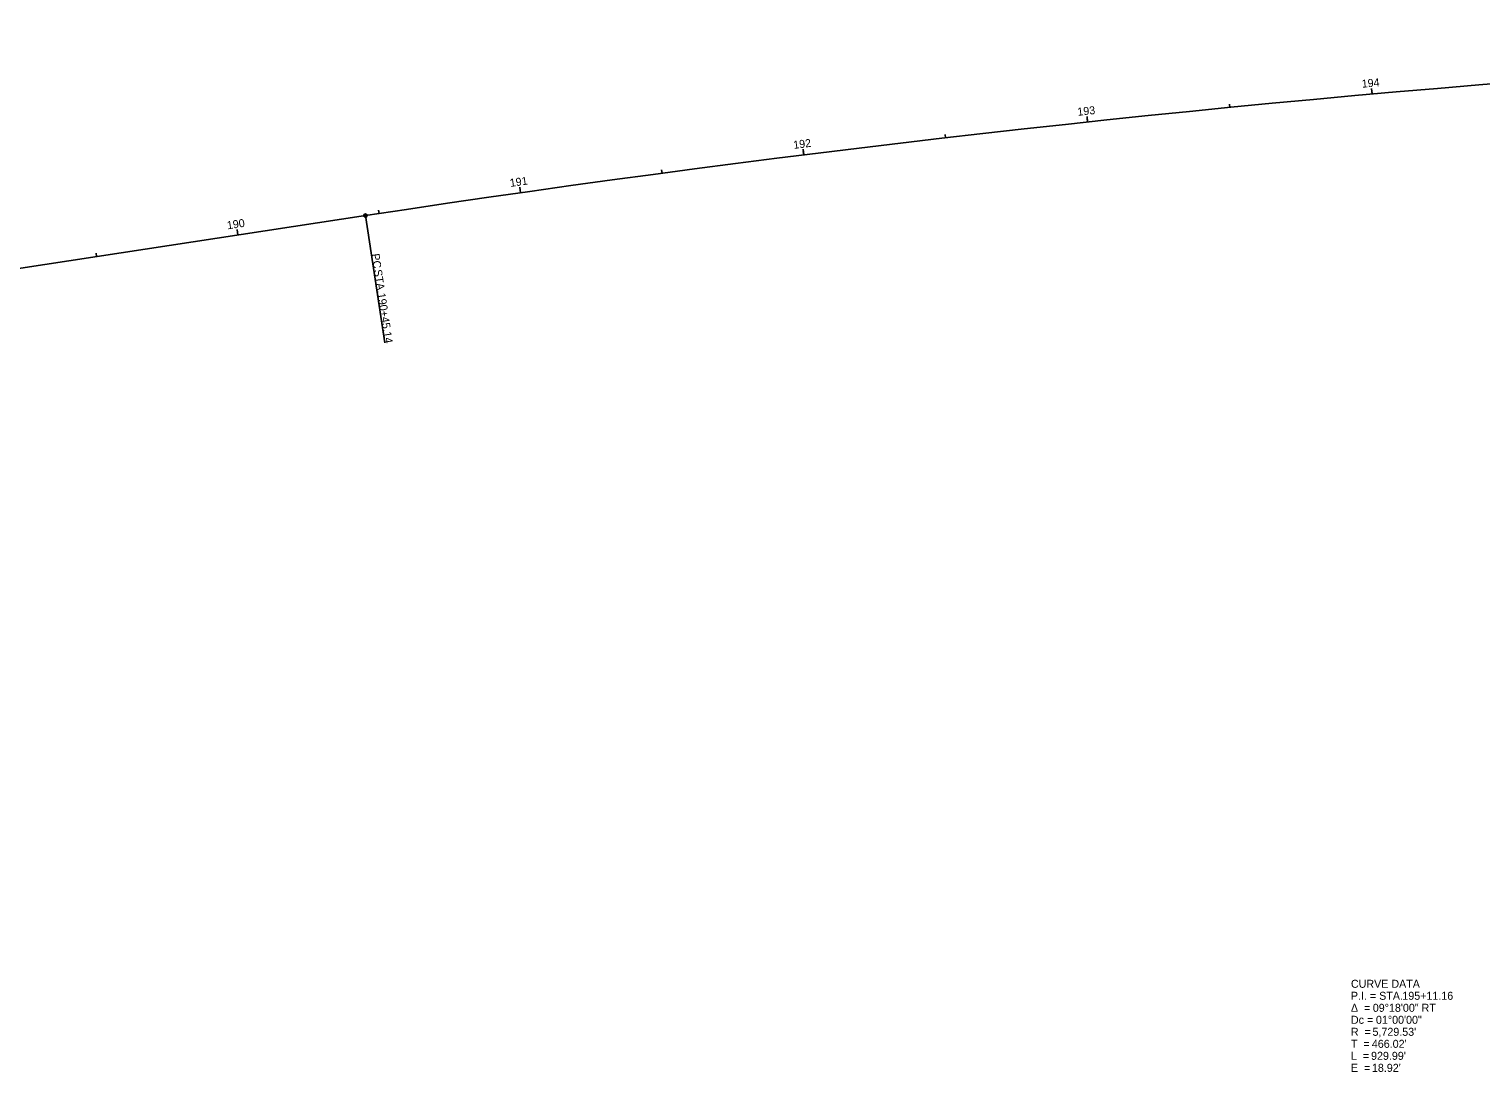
# Model space of a CAD drawing. Extents: x 1501024 to 1508874, y 327839 to 328839.
# Drawn here: x 1506902 to 1507410, y 327898 to 328263 of the extents above; entities that cross this region are included whole.
import ezdxf

# ---------------------------------------------------------------- set-up
doc = ezdxf.new("R2010")
doc.units = 0
for name, color, linetype in [('GE_X_Alignment', 7, 'Continuous'), ('GE_X_Alignment_100_Cardinal_Points', 7, 'Continuous'), ('GE_X_Alignment_100_Curve_Data', 7, 'Continuous'), ('GE_X_Alignment_100_Stations', 7, 'Continuous'), ('GE_X_Alignment_500_Cardinal_Points', 7, 'Continuous'), ('GE_X_Alignment_500_Curve_Data', 7, 'Continuous'), ('GE_X_Alignment_500_Stations', 7, 'Continuous')]:
    doc.layers.add(name, color=color, linetype=linetype)

msp = doc.modelspace()

# ---------------------------------------------------------------- linework, layer by layer
at = {"layer": 'GE_X_Alignment'}
msp.add_line((1506214.56, 328075.36), (1507019.33, 328197.87), dxfattribs=at)
msp.add_arc((1507881.6, 322533.59), 5729.53, 89.35563, 98.65563, dxfattribs=at)
at = {"layer": 'GE_X_Alignment_100_Cardinal_Points'}
msp.add_line((1507019.33, 328197.87), (1507026.1, 328153.38), dxfattribs=at)
msp.add_circle((1507019.33, 328197.87), 0.6, dxfattribs=at)
at = {"layer": 'GE_X_Alignment_100_Stations'}
for p, q in [((1507371.58, 328240.38), (1507371.4, 328242.37)), ((1507321.8, 328235.71), (1507321.68, 328236.9)), ((1507272.06, 328230.61), (1507271.84, 328232.59)), ((1507222.36, 328225.07), (1507222.23, 328226.26)), ((1507172.72, 328219.1), (1507172.47, 328221.08)), ((1507123.13, 328212.7), (1507122.97, 328213.89)), ((1507073.6, 328205.86), (1507073.32, 328207.84)), ((1507024.13, 328198.59), (1507023.95, 328199.78)), ((1506974.7, 328191.07), (1506974.4, 328193.05)), ((1506925.27, 328183.55), (1506925.09, 328184.73))]:
    msp.add_line(p, q, dxfattribs=at)
at = {"layer": 'GE_X_Alignment_500_Cardinal_Points'}
msp.add_line((1507019.33, 328197.87), (1507026.1, 328153.38), dxfattribs=at)
msp.add_circle((1507019.33, 328197.87), 0.6, dxfattribs=at)
at = {"layer": 'GE_X_Alignment_500_Stations'}
for p, q in [((1507371.58, 328240.38), (1507371.47, 328241.57)), ((1507272.06, 328230.61), (1507271.93, 328231.8)), ((1507172.72, 328219.1), (1507172.57, 328220.29)), ((1507073.6, 328205.86), (1507073.43, 328207.05)), ((1506974.7, 328191.07), (1506974.4, 328193.05))]:
    msp.add_line(p, q, dxfattribs=at)

# ---------------------------------------------------------------- texts
at = {"layer": 'GE_X_Alignment_100_Cardinal_Points'}
for s, p in [('PC', (1507021.42, 328184.38)), (' STA. ', (1507022.12, 328179.83)), ('190+45.14', (1507023.52, 328170.61))]:
    msp.add_text(s, height=2.8, rotation=278.6556, dxfattribs=at).set_placement(p)
at = {"layer": 'GE_X_Alignment_100_Curve_Data'}
for s, p in [('CURVE DATA', (1507364.19, 327927.77)), ('Δ  = ', (1507364.19, 327919.37)), ('P.I. = STA. ', (1507364.19, 327923.57)), ('09°18\'00" RT', (1507371.84, 327919.37)), ('195+11.16', (1507382.18, 327923.57)), ('Dc = ', (1507364.19, 327915.17)), ('01°00\'00"', (1507372.94, 327915.17)), ('R  = ', (1507364.19, 327910.97)), ("5,729.53'", (1507371.73, 327910.97)), ('T  = ', (1507364.19, 327906.77)), ("466.02'", (1507371.51, 327906.77)), ('L  = ', (1507364.19, 327902.57)), ('E  = ', (1507364.19, 327898.37)), ("929.99'", (1507371.23, 327902.57)), ("18.92'", (1507371.54, 327898.37))]:
    msp.add_text(s, height=2.8, dxfattribs=at).set_placement(p)
at = {"layer": 'GE_X_Alignment_100_Stations'}
for s, rotation, p in [('194', 5.107, (1507368.09, 328242.57)), ('193', 6.107, (1507268.61, 328232.75)), ('192', 7.1071, (1507169.23, 328221.18)), ('191', 8.1071, (1507070.06, 328207.88)), ('190', 8.6556, (1506971.1, 328193.05))]:
    msp.add_text(s, height=2.8, rotation=rotation, dxfattribs=at).set_placement(p)
at = {"layer": 'GE_X_Alignment_500_Cardinal_Points'}
for s, p in [('PC', (1507021.42, 328184.38)), (' STA. ', (1507022.12, 328179.83)), ('190+45.14', (1507023.52, 328170.61))]:
    msp.add_text(s, height=2.8, rotation=278.6556, dxfattribs=at).set_placement(p)
at = {"layer": 'GE_X_Alignment_500_Curve_Data'}
for s, p in [('CURVE DATA', (1507364.19, 327927.77)), ('Δ  = ', (1507364.19, 327919.37)), ('P.I. = STA. ', (1507364.19, 327923.57)), ('09°18\'00" RT', (1507371.84, 327919.37)), ('195+11.16', (1507382.18, 327923.57)), ('Dc = ', (1507364.19, 327915.17)), ('01°00\'00"', (1507372.94, 327915.17)), ('R  = ', (1507364.19, 327910.97)), ("5,729.53'", (1507371.73, 327910.97)), ('T  = ', (1507364.19, 327906.77)), ("466.02'", (1507371.51, 327906.77)), ('L  = ', (1507364.19, 327902.57)), ('E  = ', (1507364.19, 327898.37)), ("929.99'", (1507371.23, 327902.57)), ("18.92'", (1507371.54, 327898.37))]:
    msp.add_text(s, height=2.8, dxfattribs=at).set_placement(p)
at = {"layer": 'GE_X_Alignment_500_Stations'}
msp.add_text('190', height=2.8, rotation=8.6556, dxfattribs=at).set_placement((1506971.1, 328193.05))

doc.saveas('drawing.dxf')
